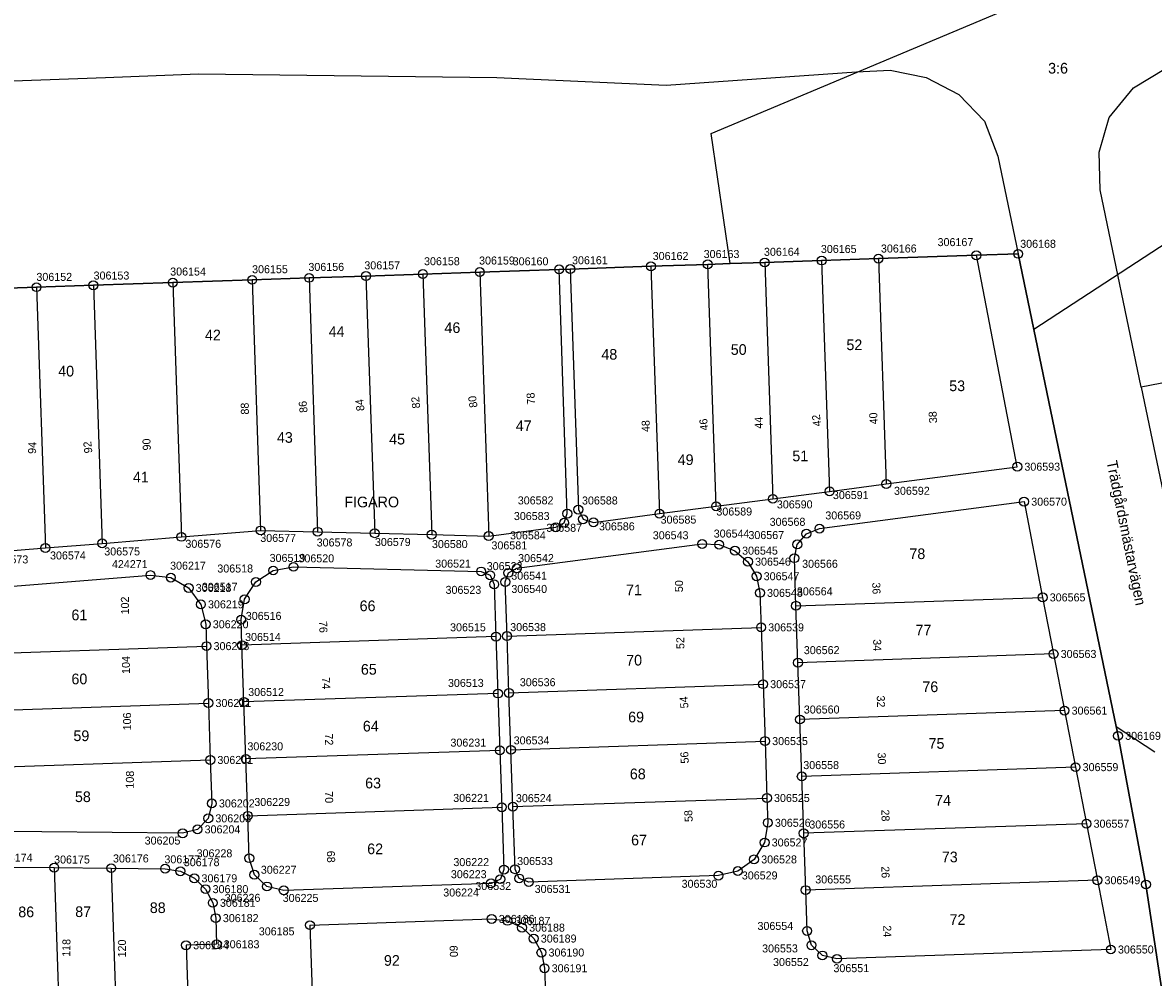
# Model space of a CAD drawing. Extents: x 141995 to 152570, y 6580184 to 6586000.
# Drawn here: x 142245.6 to 142372.8, y 6585245 to 6585352.4 of the extents above; entities that cross this region are included whole.
import ezdxf

# ---------------------------------------------------------------- set-up
doc = ezdxf.new("R2010")
doc.units = 0
for name, color, linetype in [('Level 10', 7, 'Continuous'), ('Level 13', 7, 'Continuous'), ('Level 40', 7, 'Continuous'), ('Level 5', 7, 'Continuous'), ('Level 51', 7, 'Continuous'), ('Level 53', 7, 'Continuous'), ('Level 54', 7, 'Continuous'), ('Level 58', 7, 'Continuous'), ('Level 59', 7, 'Continuous'), ('Level 6', 7, 'Continuous'), ('Level 7', 7, 'Continuous')]:
    doc.layers.add(name, color=color, linetype=linetype)

msp = doc.modelspace()

# ---------------------------------------------------------------- linework, layer by layer
at = {"layer": 'Level 10'}
for centre in [(142329.08, 6585325.45), (142335.48, 6585325.67), (142341.87, 6585325.89), (142352.88, 6585326.26), (142357.58, 6585326.42), (142290.65, 6585324.15), (142297.05, 6585324.37), (142305.97, 6585324.67), (142307.22, 6585324.71), (142316.29, 6585325.02), (142322.68, 6585325.24), (142253.6, 6585322.89), (142262.53, 6585323.19), (142271.46, 6585323.5), (142277.86, 6585323.72), (142284.25, 6585323.93), (142247.21, 6585322.67), (142357.48, 6585302.48), (142342.75, 6585300.54), (142330, 6585298.87), (142336.37, 6585299.71), (142308.13, 6585297.66), (142323.62, 6585298.03), (142358.24, 6585298.55), (142306.54, 6585296.18), (142306.89, 6585297.2), (142308.66, 6585296.57), (142309.83, 6585296.22), (142317.25, 6585297.2), (142272.41, 6585295.31), (142278.82, 6585295.16), (142285.23, 6585295), (142291.64, 6585294.84), (142305.59, 6585295.67), (142333.77, 6585294.94), (142335.24, 6585295.52), (142254.59, 6585293.86), (142263.5, 6585294.59), (142298.05, 6585294.68), (142322.05, 6585293.79), (142323.96, 6585293.72), (142332.75, 6585293.74), (142248.21, 6585293.34), (142325.74, 6585293.03), (142276.11, 6585291.22), (142301.21, 6585291.06), (142327.2, 6585291.8), (142332.42, 6585292.19), (142260.02, 6585290.29), (142262.31, 6585290.01), (142273.82, 6585290.81), (142297.2, 6585290.7), (142298.22, 6585290.27), (142300.26, 6585290.54), (142328.17, 6585290.16), (142264.31, 6585288.85), (142271.88, 6585289.52), (142298.67, 6585289.25), (142299.91, 6585289.52), (142270.61, 6585287.57), (142328.55, 6585288.29), (142360.33, 6585287.78), (142265.69, 6585287), (142332.6, 6585286.84), (142266.23, 6585284.76), (142270.22, 6585285.28), (142298.87, 6585283.37), (142300.11, 6585283.43), (142328.68, 6585284.41), (142266.32, 6585282.3), (142270.31, 6585282.41), (142361.56, 6585281.42), (142332.82, 6585280.44), (142299.09, 6585276.97), (142300.33, 6585277.04), (142328.9, 6585278.02), (142266.53, 6585275.9), (142270.53, 6585276.02), (142362.79, 6585275.05), (142333.04, 6585274.05), (142368.81, 6585272.21), (142300.55, 6585270.64), (142329.12, 6585271.62), (142266.75, 6585269.5), (142270.75, 6585269.62), (142299.3, 6585270.58), (142364.03, 6585268.69), (142333.25, 6585267.65), (142266.92, 6585264.61), (142300.77, 6585264.25), (142329.33, 6585265.22), (142270.97, 6585263.22), (142299.52, 6585264.18), (142265.31, 6585261.69), (142266.52, 6585262.93), (142329.43, 6585262.43), (142365.26, 6585262.33), (142263.64, 6585261.25), (142333.47, 6585261.25), (142329.07, 6585260.21), (142271.13, 6585258.45), (142327.88, 6585258.31), (142249.2, 6585257.39), (142255.61, 6585257.33), (142261.67, 6585257.27), (142263.39, 6585256.98), (142299.76, 6585257.17), (142301.01, 6585257.21), (142326.06, 6585257), (142264.96, 6585256.19), (142271.7, 6585256.59), (142298.31, 6585255.62), (142299.36, 6585256.09), (142301.48, 6585256.17), (142302.56, 6585255.76), (142323.88, 6585256.49), (142366.49, 6585255.97), (142371.95, 6585255.49), (142266.21, 6585254.97), (142273.12, 6585255.27), (142275.01, 6585254.83), (142333.69, 6585254.86), (142267.03, 6585253.43), (142267.36, 6585251.71), (142298.38, 6585251.62), (142277.95, 6585250.92), (142300.17, 6585251.4), (142301.8, 6585250.64), (142333.85, 6585250.27), (142303.11, 6585249.41), (142264.02, 6585248.66), (142267.46, 6585248.77), (142303.98, 6585247.83), (142334.34, 6585248.66), (142368, 6585248.18), (142335.57, 6585247.51), (142337.21, 6585247.13), (142304.33, 6585246.07)]:
    msp.add_circle(centre, 0.5, dxfattribs=at)
at = {"layer": 'Level 13'}
for points in [[(142219.63, 6585344.99), (142254.95, 6585346.27)], [(142254.95, 6585346.27), (142265.43, 6585346.65)], [(142265.43, 6585346.65), (142298.97, 6585346.26)], [(142298.97, 6585346.26), (142317.99, 6585345.39)], [(142317.99, 6585345.39), (142339.41, 6585346.88)], [(142339.41, 6585346.88), (142343.18, 6585347.09)], [(142343.18, 6585347.09), (142347.25, 6585346.26)], [(142347.25, 6585346.26), (142350.92, 6585344.36)], [(142370.55, 6585345.1), (142374.14, 6585347.28)], [(142367.81, 6585341.76), (142370.55, 6585345.1)], [(142350.92, 6585344.36), (142353.8, 6585341.33)], [(142353.8, 6585341.33), (142355.3, 6585337.42)], [(142366.67, 6585337.86), (142367.81, 6585341.76)], [(142355.3, 6585337.42), (142357.58, 6585326.42)], [(142366.79, 6585333.62), (142366.67, 6585337.86)], [(142371.41, 6585311.41), (142366.79, 6585333.62)]]:
    msp.add_lwpolyline(points, dxfattribs=at)
at = {"layer": 'Level 5'}
for points in [[(142323.06, 6585339.95), (142377.49, 6585362.87)], [(142325.2, 6585325.32), (142323.06, 6585339.95)], [(142393.01, 6585339.88), (142359.34, 6585317.91)], [(142335.48, 6585325.67), (142341.87, 6585325.89)], [(142341.87, 6585325.89), (142352.88, 6585326.26)], [(142352.88, 6585326.26), (142357.58, 6585326.42)], [(142357.58, 6585326.42), (142359.34, 6585317.91)], [(142297.05, 6585324.37), (142305.97, 6585324.67)], [(142305.97, 6585324.67), (142307.22, 6585324.71)], [(142307.22, 6585324.71), (142316.29, 6585325.02)], [(142316.29, 6585325.02), (142322.68, 6585325.24)], [(142322.68, 6585325.24), (142325.2, 6585325.32)], [(142325.2, 6585325.32), (142329.08, 6585325.45)], [(142329.08, 6585325.45), (142335.48, 6585325.67)], [(142262.53, 6585323.19), (142271.46, 6585323.5)], [(142271.46, 6585323.5), (142277.86, 6585323.72)], [(142277.86, 6585323.72), (142284.25, 6585323.93)], [(142284.25, 6585323.93), (142290.65, 6585324.15)], [(142290.65, 6585324.15), (142297.05, 6585324.37)], [(142240.81, 6585322.46), (142247.21, 6585322.67)], [(142247.21, 6585322.67), (142253.6, 6585322.89)], [(142253.6, 6585322.89), (142262.53, 6585323.19)], [(142359.34, 6585317.91), (142368.59, 6585273.25)], [(142368.59, 6585273.25), (142368.81, 6585272.21)], [(142368.59, 6585273.25), (142372.95, 6585270.41)], [(142368.81, 6585272.21), (142371.95, 6585255.49)], [(142371.95, 6585255.49), (142374.5, 6585238.65)]]:
    msp.add_lwpolyline(points, dxfattribs=at)
at = {"layer": 'Level 6'}
msp.add_lwpolyline([(142374.5, 6585238.65), (142371.95, 6585255.49), (142368.81, 6585272.21), (142368.59, 6585273.25), (142359.34, 6585317.91), (142357.58, 6585326.42), (142352.88, 6585326.26), (142341.87, 6585325.89), (142335.48, 6585325.67), (142329.08, 6585325.45), (142325.2, 6585325.32), (142322.68, 6585325.24), (142316.29, 6585325.02), (142307.22, 6585324.71), (142305.97, 6585324.67), (142297.05, 6585324.37), (142290.65, 6585324.15), (142284.25, 6585323.93), (142277.86, 6585323.72), (142271.46, 6585323.5), (142262.53, 6585323.19), (142253.6, 6585322.89), (142247.21, 6585322.67), (142240.81, 6585322.46)], dxfattribs=at)
msp.add_lwpolyline([(142374.4, 6585297.05), (142386.09, 6585299.25), (142382.88, 6585313.64), (142371.41, 6585311.41)], close=True, dxfattribs=at)
at = {"layer": 'Level 7'}
for points in [[(142341.87, 6585325.89), (142342.75, 6585300.54)], [(142357.48, 6585302.48), (142352.88, 6585326.26)], [(142306.89, 6585297.2), (142305.97, 6585324.67)], [(142307.22, 6585324.71), (142308.13, 6585297.66)], [(142316.29, 6585325.02), (142317.25, 6585297.2)], [(142323.62, 6585298.03), (142322.68, 6585325.24)], [(142329.08, 6585325.45), (142330, 6585298.87)], [(142335.48, 6585325.67), (142336.37, 6585299.71)], [(142271.46, 6585323.5), (142272.41, 6585295.31)], [(142277.86, 6585323.72), (142278.82, 6585295.16)], [(142284.25, 6585323.93), (142285.23, 6585295)], [(142290.65, 6585324.15), (142291.64, 6585294.84)], [(142297.05, 6585324.37), (142298.05, 6585294.68)], [(142247.21, 6585322.67), (142248.21, 6585293.34)], [(142253.6, 6585322.89), (142254.59, 6585293.86)], [(142262.53, 6585323.19), (142263.5, 6585294.59)], [(142342.75, 6585300.54), (142357.48, 6585302.48)], [(142336.37, 6585299.71), (142342.75, 6585300.54)], [(142330, 6585298.87), (142336.37, 6585299.71)], [(142317.25, 6585297.2), (142323.62, 6585298.03)], [(142323.62, 6585298.03), (142330, 6585298.87)], [(142335.24, 6585295.52), (142358.24, 6585298.55)], [(142358.24, 6585298.55), (142360.33, 6585287.78)], [(142306.54, 6585296.18), (142306.89, 6585297.2)], [(142308.13, 6585297.66), (142308.66, 6585296.57)], [(142308.66, 6585296.57), (142309.83, 6585296.22)], [(142309.83, 6585296.22), (142317.25, 6585297.2)], [(142263.5, 6585294.59), (142272.41, 6585295.31)], [(142272.41, 6585295.31), (142278.82, 6585295.16)], [(142298.05, 6585294.68), (142305.59, 6585295.67)], [(142305.59, 6585295.67), (142306.54, 6585296.18)], [(142333.77, 6585294.94), (142335.24, 6585295.52)], [(142254.59, 6585293.86), (142263.5, 6585294.59)], [(142278.82, 6585295.16), (142285.23, 6585295)], [(142285.23, 6585295), (142291.64, 6585294.84)], [(142291.64, 6585294.84), (142298.05, 6585294.68)], [(142332.75, 6585293.74), (142333.77, 6585294.94)], [(142241.82, 6585292.83), (142248.21, 6585293.34)], [(142248.21, 6585293.34), (142254.59, 6585293.86)], [(142301.21, 6585291.06), (142322.05, 6585293.79)], [(142322.05, 6585293.79), (142323.96, 6585293.72)], [(142323.96, 6585293.72), (142325.74, 6585293.03)], [(142325.74, 6585293.03), (142327.2, 6585291.8)], [(142332.42, 6585292.19), (142332.75, 6585293.74)], [(142327.2, 6585291.8), (142328.17, 6585290.16)], [(142332.6, 6585286.84), (142332.42, 6585292.19)], [(142238.94, 6585288.58), (142260.02, 6585290.29)], [(142260.02, 6585290.29), (142262.31, 6585290.01)], [(142271.88, 6585289.52), (142273.82, 6585290.81)], [(142273.82, 6585290.81), (142276.11, 6585291.22)], [(142276.11, 6585291.22), (142297.2, 6585290.7)], [(142297.2, 6585290.7), (142298.22, 6585290.27)], [(142298.22, 6585290.27), (142298.67, 6585289.25)], [(142299.91, 6585289.52), (142300.26, 6585290.54)], [(142300.26, 6585290.54), (142301.21, 6585291.06)], [(142328.17, 6585290.16), (142328.55, 6585288.29)], [(142262.31, 6585290.01), (142264.31, 6585288.85)], [(142270.61, 6585287.57), (142271.88, 6585289.52)], [(142298.67, 6585289.25), (142298.87, 6585283.37)], [(142300.11, 6585283.43), (142299.91, 6585289.52)], [(142264.31, 6585288.85), (142265.69, 6585287)], [(142328.55, 6585288.29), (142328.68, 6585284.41)], [(142332.6, 6585286.84), (142360.33, 6585287.78)], [(142360.33, 6585287.78), (142361.56, 6585281.42)], [(142265.69, 6585287), (142266.23, 6585284.76)], [(142270.22, 6585285.28), (142270.61, 6585287.57)], [(142332.82, 6585280.44), (142332.6, 6585286.84)], [(142270.31, 6585282.41), (142270.22, 6585285.28)], [(142266.23, 6585284.76), (142266.32, 6585282.3)], [(142300.11, 6585283.43), (142328.68, 6585284.41)], [(142328.68, 6585284.41), (142328.9, 6585278.02)], [(142298.87, 6585283.37), (142270.31, 6585282.41)], [(142298.87, 6585283.37), (142299.09, 6585276.97)], [(142300.33, 6585277.04), (142300.11, 6585283.43)], [(142237.75, 6585281.33), (142266.32, 6585282.3)], [(142266.32, 6585282.3), (142266.53, 6585275.9)], [(142270.53, 6585276.02), (142270.31, 6585282.41)], [(142361.56, 6585281.42), (142332.82, 6585280.44)], [(142361.56, 6585281.42), (142362.79, 6585275.05)], [(142333.04, 6585274.05), (142332.82, 6585280.44)], [(142300.33, 6585277.04), (142328.9, 6585278.02)], [(142328.9, 6585278.02), (142329.12, 6585271.62)], [(142299.09, 6585276.97), (142270.53, 6585276.02)], [(142299.09, 6585276.97), (142299.3, 6585270.58)], [(142300.55, 6585270.64), (142300.33, 6585277.04)], [(142237.97, 6585274.93), (142266.53, 6585275.9)], [(142266.53, 6585275.9), (142266.75, 6585269.5)], [(142270.75, 6585269.62), (142270.53, 6585276.02)], [(142362.79, 6585275.05), (142333.04, 6585274.05)], [(142362.79, 6585275.05), (142364.03, 6585268.69)], [(142333.25, 6585267.65), (142333.04, 6585274.05)], [(142300.55, 6585270.64), (142329.12, 6585271.62)], [(142329.12, 6585271.62), (142329.33, 6585265.22)], [(142299.3, 6585270.58), (142270.75, 6585269.62)], [(142299.3, 6585270.58), (142299.52, 6585264.18)], [(142300.77, 6585264.25), (142300.55, 6585270.64)], [(142238.19, 6585268.54), (142266.75, 6585269.5)], [(142266.75, 6585269.5), (142266.92, 6585264.61)], [(142270.97, 6585263.22), (142270.75, 6585269.62)], [(142364.03, 6585268.69), (142333.25, 6585267.65)], [(142364.03, 6585268.69), (142365.26, 6585262.33)], [(142333.47, 6585261.25), (142333.25, 6585267.65)], [(142300.77, 6585264.25), (142329.33, 6585265.22)], [(142329.33, 6585265.22), (142329.43, 6585262.43)], [(142266.92, 6585264.61), (142266.52, 6585262.93)], [(142270.97, 6585263.22), (142299.52, 6585264.18)], [(142299.52, 6585264.18), (142299.76, 6585257.17)], [(142301.01, 6585257.21), (142300.77, 6585264.25)], [(142266.52, 6585262.93), (142265.31, 6585261.69)], [(142271.13, 6585258.45), (142270.97, 6585263.22)], [(142329.43, 6585262.43), (142329.07, 6585260.21)], [(142365.26, 6585262.33), (142333.47, 6585261.25)], [(142365.26, 6585262.33), (142366.49, 6585255.97)], [(142263.64, 6585261.25), (142239.86, 6585261.48)], [(142265.31, 6585261.69), (142263.64, 6585261.25)], [(142333.69, 6585254.86), (142333.47, 6585261.25)], [(142329.07, 6585260.21), (142327.88, 6585258.31)], [(142271.7, 6585256.59), (142271.13, 6585258.45)], [(142242.79, 6585257.45), (142249.2, 6585257.39)], [(142249.2, 6585257.39), (142255.61, 6585257.33)], [(142249.2, 6585257.39), (142250.06, 6585231.77)], [(142255.61, 6585257.33), (142261.67, 6585257.27)], [(142255.61, 6585257.33), (142256.46, 6585231.99)], [(142261.67, 6585257.27), (142263.39, 6585256.98)], [(142299.76, 6585257.17), (142299.36, 6585256.09)], [(142301.48, 6585256.17), (142301.01, 6585257.21)], [(142327.88, 6585258.31), (142326.06, 6585257)], [(142263.39, 6585256.98), (142264.96, 6585256.19)], [(142264.96, 6585256.19), (142266.21, 6585254.97)], [(142273.12, 6585255.27), (142271.7, 6585256.59)], [(142299.36, 6585256.09), (142298.31, 6585255.62)], [(142302.56, 6585255.76), (142301.48, 6585256.17)], [(142323.88, 6585256.49), (142302.56, 6585255.76)], [(142326.06, 6585257), (142323.88, 6585256.49)], [(142366.49, 6585255.97), (142333.69, 6585254.86)], [(142366.49, 6585255.97), (142368, 6585248.18)], [(142266.21, 6585254.97), (142267.03, 6585253.43)], [(142275.01, 6585254.83), (142273.12, 6585255.27)], [(142298.31, 6585255.62), (142275.01, 6585254.83)], [(142333.85, 6585250.27), (142333.69, 6585254.86)], [(142267.03, 6585253.43), (142267.36, 6585251.71)], [(142267.36, 6585251.71), (142267.46, 6585248.77)], [(142277.95, 6585250.92), (142298.38, 6585251.62)], [(142277.95, 6585250.92), (142278.24, 6585242.37)], [(142298.38, 6585251.62), (142300.17, 6585251.4)], [(142300.17, 6585251.4), (142301.8, 6585250.64)], [(142301.8, 6585250.64), (142303.11, 6585249.41)], [(142334.34, 6585248.66), (142333.85, 6585250.27)], [(142267.46, 6585248.77), (142264.02, 6585248.66)], [(142264.02, 6585248.66), (142264.36, 6585238.66)], [(142303.11, 6585249.41), (142303.98, 6585247.83)], [(142335.57, 6585247.51), (142334.34, 6585248.66)], [(142303.98, 6585247.83), (142304.33, 6585246.07)], [(142337.21, 6585247.13), (142335.57, 6585247.51)], [(142368, 6585248.18), (142337.21, 6585247.13)], [(142304.33, 6585246.07), (142304.42, 6585243.25)]]:
    msp.add_lwpolyline(points, dxfattribs=at)

# ---------------------------------------------------------------- texts
at = {"layer": 'Level 40'}
msp.add_text('Trädgårdsmästarvägen', height=1.2, rotation=281.454, dxfattribs=at).set_placement((142367.51, 6585303.05))
at = {"layer": 'Level 51'}
for s, p in [('3:6', (142360.95, 6585346.7)), ('44', (142280.06, 6585317.08)), ('46', (142293.08, 6585317.52)), ('42', (142266.15, 6585316.69)), ('48', (142310.72, 6585314.52)), ('50', (142325.27, 6585315.06)), ('52', (142338.27, 6585315.59)), ('40', (142249.65, 6585312.63)), ('53', (142349.83, 6585310.98)), ('47', (142301.1, 6585306.48)), ('43', (142274.24, 6585305.17)), ('45', (142286.86, 6585304.98)), ('51', (142332.19, 6585303.09)), ('49', (142319.3, 6585302.67)), ('41', (142258.05, 6585300.71)), ('78', (142345.35, 6585292.09)), ('71', (142313.49, 6585288.02)), ('61', (142251.14, 6585285.21)), ('66', (142283.54, 6585286.23)), ('77', (142346.04, 6585283.51)), ('70', (142313.51, 6585280.12)), ('65', (142283.68, 6585279.09)), ('60', (142251.14, 6585278.01)), ('76', (142346.81, 6585277.13)), ('69', (142313.73, 6585273.73)), ('64', (142283.9, 6585272.7)), ('59', (142251.36, 6585271.62)), ('75', (142347.51, 6585270.75)), ('68', (142313.92, 6585267.33)), ('63', (142284.16, 6585266.3)), ('58', (142251.53, 6585264.76)), ('74', (142348.24, 6585264.37)), ('67', (142314.06, 6585259.89)), ('62', (142284.39, 6585258.9)), ('73', (142349, 6585257.99)), ('87', (142251.56, 6585251.83)), ('72', (142349.87, 6585250.95)), ('92', (142286.27, 6585246.35))]:
    msp.add_text(s, height=1.2, rotation=0.0526, dxfattribs=at).set_placement(p)
at = {"layer": 'Level 53'}
for s, p in [('306164', (142329, 6585326.2)), ('306165', (142335.4, 6585326.52)), ('306166', (142342.15, 6585326.57)), ('306167', (142348.52, 6585327.29)), ('306168', (142357.81, 6585327.1)), ('306158', (142290.78, 6585325.14)), ('306159', (142296.97, 6585325.22)), ('306160', (142300.75, 6585325.13)), ('306161', (142307.42, 6585325.25)), ('306162', (142316.49, 6585325.73)), ('306163', (142322.22, 6585325.95)), ('306154', (142262.24, 6585323.98)), ('306155', (142271.45, 6585324.24)), ('306156', (142277.78, 6585324.5)), ('306157', (142284.07, 6585324.68)), ('306152', (142247.2, 6585323.38)), ('306153', (142253.63, 6585323.53)), ('306593', (142358.28, 6585302.03)), ('306582', (142301.32, 6585298.24)), ('306588', (142308.54, 6585298.23)), ('306591', (142336.75, 6585298.84)), ('306592', (142343.62, 6585299.32)), ('306589', (142323.65, 6585296.99)), ('306590', (142330.45, 6585297.79)), ('306570', (142359.05, 6585298.1)), ('306583', (142300.88, 6585296.48)), ('306585', (142317.38, 6585296.08)), ('306568', (142329.64, 6585295.83)), ('306569', (142335.9, 6585296.55)), ('306587', (142304.53, 6585295.16)), ('306586', (142310.45, 6585295.32)), ('306543', (142316.5, 6585294.32)), ('306544', (142323.35, 6585294.51)), ('306567', (142327.25, 6585294.34)), ('306576', (142263.95, 6585293.36)), ('306577', (142272.37, 6585294.02)), ('306578', (142278.71, 6585293.51)), ('306579', (142285.26, 6585293.56)), ('306580', (142291.67, 6585293.33)), ('306581', (142298.36, 6585293.18)), ('306584', (142300.45, 6585294.31)), ('306574', (142248.73, 6585292.05)), ('306575', (142254.83, 6585292.5)), ('306545', (142326.54, 6585292.59)), ('306573', (142242.27, 6585291.6)), ('424271', (142255.69, 6585291.07)), ('306217', (142262.23, 6585290.9)), ('306518', (142267.54, 6585290.58)), ('306519', (142273.42, 6585291.77)), ('306520', (142276.66, 6585291.72)), ('306521', (142292.04, 6585291.13)), ('306522', (142297.83, 6585290.85)), ('306542', (142301.36, 6585291.75)), ('306546', (142328, 6585291.35)), ('306566', (142333.29, 6585291.11)), ('306541', (142300.59, 6585289.77)), ('306547', (142328.97, 6585289.71)), ('306218', (142265.11, 6585288.4)), ('306517', (142265.8, 6585288.52)), ('306523', (142293.2, 6585288.18)), ('306540', (142300.6, 6585288.28)), ('306564', (142332.7, 6585288.01)), ('306548', (142329.35, 6585287.84)), ('306565', (142361.13, 6585287.33)), ('306219', (142266.49, 6585286.55)), ('306220', (142267.03, 6585284.31)), ('306516', (142270.74, 6585285.25)), ('306515', (142293.71, 6585283.97)), ('306538', (142300.47, 6585283.99)), ('306539', (142329.48, 6585283.96)), ('306213', (142267.12, 6585281.85)), ('306514', (142270.66, 6585282.88)), ('306562', (142333.48, 6585281.4)), ('306563', (142362.36, 6585280.97)), ('306512', (142271.01, 6585276.69)), ('306513', (142293.47, 6585277.71)), ('306536', (142301.55, 6585277.79)), ('306537', (142329.7, 6585277.57)), ('306211', (142267.33, 6585275.45)), ('306560', (142333.48, 6585274.72)), ('306561', (142363.59, 6585274.6)), ('306169', (142369.61, 6585271.76)), ('306230', (142270.92, 6585270.58)), ('306231', (142293.75, 6585271)), ('306534', (142300.86, 6585271.25)), ('306535', (142329.92, 6585271.17)), ('306201', (142267.55, 6585269.05)), ('306558', (142333.42, 6585268.47)), ('306559', (142364.83, 6585268.24)), ('306202', (142267.72, 6585264.16)), ('306229', (142271.7, 6585264.32)), ('306221', (142294.06, 6585264.78)), ('306524', (142301.11, 6585264.75)), ('306525', (142330.13, 6585264.77)), ('306203', (142267.32, 6585262.48)), ('306526', (142330.23, 6585261.98)), ('306556', (142334.1, 6585261.79)), ('306557', (142366.06, 6585261.88)), ('306204', (142266.11, 6585261.24)), ('306205', (142259.37, 6585259.98)), ('306527', (142329.87, 6585259.77)), ('306174', (142242.75, 6585258.06)), ('306175', (142249.19, 6585257.85)), ('306176', (142255.81, 6585257.97)), ('306177', (142261.59, 6585257.87)), ('306178', (142263.77, 6585257.55)), ('306228', (142265.21, 6585258.55)), ('306222', (142294.08, 6585257.56)), ('306533', (142301.25, 6585257.68)), ('306528', (142328.69, 6585257.86)), ('306227', (142272.43, 6585256.7)), ('306223', (142293.8, 6585256.2)), ('306179', (142265.76, 6585255.74)), ('306530', (142319.74, 6585255.12)), ('306529', (142326.51, 6585256.06)), ('306555', (142334.77, 6585255.61)), ('306549', (142367.29, 6585255.52)), ('306180', (142267.01, 6585254.52)), ('306224', (142292.94, 6585254.14)), ('306532', (142296.55, 6585254.87)), ('306531', (142303.22, 6585254.54)), ('306181', (142267.83, 6585252.98)), ('306226', (142268.37, 6585253.54)), ('306225', (142274.89, 6585253.53)), ('306182', (142268.16, 6585251.26)), ('306186', (142299.19, 6585251.17)), ('306187', (142300.97, 6585250.95)), ('306188', (142302.6, 6585250.19)), ('306554', (142328.27, 6585250.38)), ('306185', (142272.2, 6585249.77)), ('306189', (142303.91, 6585248.96)), ('306184', (142264.82, 6585248.21)), ('306183', (142268.26, 6585248.32)), ('306190', (142304.78, 6585247.39)), ('306553', (142328.79, 6585247.85)), ('306550', (142368.8, 6585247.73)), ('306552', (142330.02, 6585246.32)), ('306191', (142305.13, 6585245.62)), ('306551', (142336.81, 6585245.63))]:
    msp.add_text(s, height=0.9, rotation=0.0526, dxfattribs=at).set_placement(p)
at = {"layer": 'Level 54'}
for s, rotation, p in [('78', 94.5208, (142303.29, 6585309.51)), ('88', 91.0127, (142271.09, 6585308.35)), ('86', 95.9429, (142277.7, 6585308.59)), ('84', 96.4749, (142284.09, 6585308.79)), ('82', 96.2379, (142290.36, 6585309.08)), ('80', 97.9969, (142296.8, 6585309.18)), ('44', 91.6837, (142328.87, 6585306.77)), ('42', 96.8199, (142335.44, 6585307.06)), ('40', 93.9798, (142341.81, 6585307.27)), ('38', 93.4708, (142348.48, 6585307.4)), ('48', 91.7687, (142316.18, 6585306.39)), ('46', 96.1479, (142322.75, 6585306.6)), ('90', 92.7008, (142260.07, 6585304.33)), ('94', 87.8866, (142247.15, 6585303.91)), ('92', 95.8068, (142253.49, 6585304.04)), ('50', 89.8347, (142319.89, 6585288.37)), ('36', 271.9217, (142341.17, 6585289.46)), ('102', 90.5787, (142257.61, 6585285.87)), ('76', 271.9137, (142278.98, 6585285.12)), ('52', 90.4407, (142320.05, 6585281.98)), ('34', 271.9217, (142341.27, 6585283.06)), ('104', 90.2367, (142257.72, 6585279.18)), ('74', 271.9137, (142279.3, 6585278.79)), ('54', 94.1708, (142320.51, 6585275.33)), ('32', 271.9217, (142341.68, 6585276.73)), ('106', 90.5257, (142257.85, 6585272.83)), ('72', 271.9137, (142279.63, 6585272.46)), ('56', 92.8638, (142320.55, 6585269.12)), ('30', 271.9217, (142341.78, 6585270.32)), ('108', 89.1297, (142258.14, 6585266.27)), ('70', 271.9137, (142279.63, 6585265.96)), ('58', 93.4448, (142321, 6585262.55)), ('28', 271.9217, (142342.19, 6585263.91)), ('68', 271.9137, (142279.85, 6585259.27)), ('26', 271.9217, (142342.19, 6585257.53)), ('24', 271.9217, (142342.4, 6585250.88)), ('118', 89.0887, (142251, 6585247.35)), ('120', 89.8647, (142257.26, 6585247.29)), ('60', 271.9317, (142293.65, 6585248.64))]:
    msp.add_text(s, height=0.9, rotation=rotation, dxfattribs=at).set_placement(p)
at = {"layer": 'Level 58'}
msp.add_text('FIGARO', height=1.2, rotation=0.0526, dxfattribs=at).set_placement((142281.82, 6585297.91))
at = {"layer": 'Level 59'}
for s, p in [('88', (142259.95, 6585252.28)), ('86', (142245.16, 6585251.81))]:
    msp.add_text(s, height=1.2, rotation=0.0526, dxfattribs=at).set_placement(p)

doc.saveas('drawing.dxf')
